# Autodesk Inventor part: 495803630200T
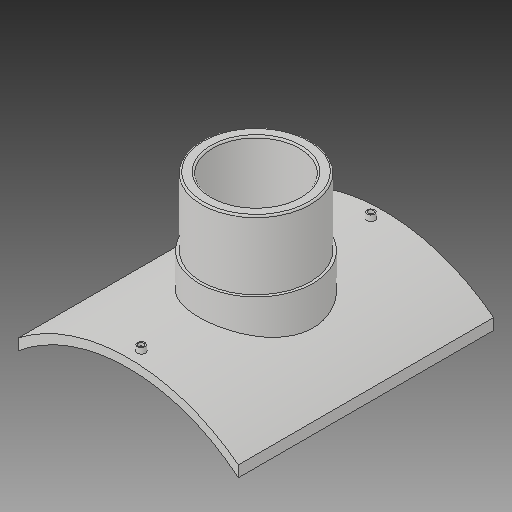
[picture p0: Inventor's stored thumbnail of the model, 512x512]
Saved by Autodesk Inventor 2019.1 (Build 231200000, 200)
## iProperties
Created: 2017-10
Part Number: 495803630200T
Material: Generic
Description: PLASSON BRANCH SADDLE  630x200
Document SubType Name: Modeling
Designer: KIM
Mass: 2754.05 g
Surface Area: 3037.44 cm^2
Volume: 2754.05 cm^3
Density: 1 g/cm^3
Appearance: Default
Author: KIM
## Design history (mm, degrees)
derived "495803.ipt"
feature "Solid1::495803.ipt"
tag "TaggingFeature1"
body "Solid1"
other parameters: "d1" = 16, "d2" = 405, "d4" = 0, "d12" = 340.6, "d13" = 14, "d14" = 211.5, "d16" = 5 deg, "d18" = 4, "d19" = 14, "d20" = 0, "d21" = 3, "d22" = 0, "d23" = 511, "d25" = 16, "d28" = 0, "d29" = 9.6, "d31" = 0, "d33" = 0, "d34" = 6.3, "d37" = 126, "d38" = 0, "d39" = 3.15, "B_" = 405, "x_" = 16, "D_" = 16
